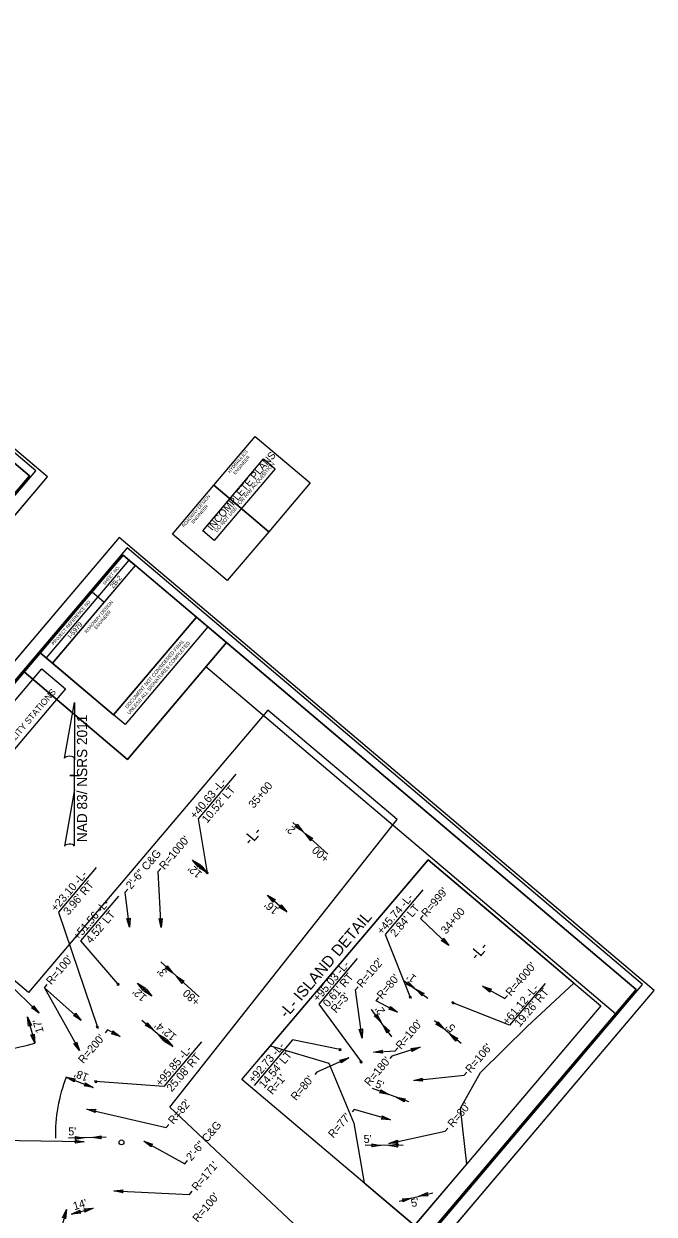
# Model space of a CAD drawing. Extents: x 1761753 to 1762923, y 422186 to 423380.
# Drawn here: x 1762529 to 1762923, y 422600 to 423344 of the extents above; entities that cross this region are included whole.
import ezdxf

# ---------------------------------------------------------------- set-up
doc = ezdxf.new("R2010")
doc.units = 0
for name, color, linetype in [('Default', 7, 'Continuous'), ('Matchline', 7, 'Continuous'), ('Old_Level_11', 7, 'Continuous'), ('Old_Level_2', 7, 'Continuous'), ('Prop Conc 2ft 6in Curb and Gutter', 7, 'Continuous'), ('Prop Conc 5in Monolithic Keyed In Island', 7, 'Continuous'), ('Prop Dimension Text', 7, 'Continuous'), ('Prop Grid Mask', 7, 'Continuous'), ('Prop Horizontal Alignment Station Label', 7, 'Continuous'), ('Prop Lane Lines', 7, 'Continuous'), ('Prop RDY Traffic Signal CELL', 7, 'Continuous'), ('Prop Shade Light', 7, 'Continuous'), ('Sheet Data Field CELL', 7, 'Continuous'), ('Sheet North Arrow CELL', 7, 'Continuous'), ('Sheet Plan CELL', 7, 'Continuous'), ('Sheet Plot Border Inside CELL', 7, 'Continuous'), ('Sheet Plot Border Outside CELL', 7, 'Continuous'), ('Sheet Symbology CELL', 7, 'Continuous')]:
    doc.layers.add(name, color=color, linetype=linetype)

# ---------------------------------------------------------------- blocks, each defined once
blk = doc.blocks.new('Terminator')
at = {"layer": 'Sheet Data Field CELL'}
blk.add_lwpolyline([(-9, 1.55), (0, 0), (-9.05, -1.6), (-7.9, 0)], close=True, dxfattribs=at)

msp = doc.modelspace()

# ---------------------------------------------------------------- linework, layer by layer
at = {"layer": 'Default'}
for p, q in [((1762643.7, 422813.72), (1762643.12, 422814.21)), ((1762644.53, 422813.02), (1762643.7, 422813.72)), ((1762588, 422744.01), (1762587.42, 422744.5)), ((1762588.84, 422743.31), (1762588, 422744.01)), ((1762770.61, 422736.01), (1762770.03, 422736.5)), ((1762771.44, 422735.31), (1762770.61, 422736.01)), ((1762797.3, 422732.43), (1762796.72, 422732.92)), ((1762798.13, 422731.73), (1762797.3, 422732.43)), ((1762575.18, 422717.23), (1762574.6, 422717.72)), ((1762576.01, 422716.53), (1762575.18, 422717.23)), ((1762726.66, 422703.17), (1762726.08, 422703.66)), ((1762727.49, 422702.47), (1762726.66, 422703.17)), ((1762739.9, 422695.46), (1762739.32, 422695.95)), ((1762740.74, 422694.76), (1762739.9, 422695.46)), ((1762574.1, 422683.22), (1762573.51, 422683.71)), ((1762574.93, 422682.51), (1762574.1, 422683.22))]:
    msp.add_line(p, q, dxfattribs=at)
at = {"layer": 'Matchline'}
for p, q in [((1762554.85, 422885.28), (1762561, 422920.05)), ((1762561.03, 422920.05), (1762561, 422920.05)), ((1762561.03, 422920.05), (1762561, 422920.05)), ((1762561.03, 422920.05), (1762561.03, 422884.2)), ((1762561.03, 422865.6), (1762561.03, 422885.25)), ((1762561.03, 422884.2), (1762561.03, 422885.21)), ((1762558.03, 422874.3), (1762558, 422874.3)), ((1762560.7, 422874.3), (1762558.03, 422874.3)), ((1762558.07, 422874.3), (1762564.07, 422874.3)), ((1762561.03, 422865.6), (1762554.77, 422830.16)), ((1762561.07, 422830.31), (1762561.03, 422865.6))]:
    msp.add_line(p, q, dxfattribs=at)
for centre, start_param, end_param in [((1762557.95, 422884.91), 0.216388, 2.908219), ((1762557.95, 422830.03), 0.201328, 3.141593)]:
    msp.add_ellipse(centre, major_axis=(3.17, -0.02), ratio=0.461098, start_param=start_param, end_param=end_param, dxfattribs=at)
at = {"layer": 'Old_Level_2'}
msp.add_lwpolyline([(1762648.26, 423021.24), (1762641.09, 423027.31), (1762679.1, 423072.18), (1762686.27, 423066.1)], close=True, dxfattribs=at)
at = {"layer": 'Prop Conc 2ft 6in Curb and Gutter'}
for points in [[(1762106.21, 422556.31), (1762536.95, 423064.78), (1762214.97, 423337.56), (1761784.22, 422829.09)], [(1762485.08, 422235.35), (1762915.83, 422743.82), (1762593.84, 423016.59), (1762163.09, 422508.12)]]:
    msp.add_lwpolyline(points, close=True, dxfattribs=at)
at = {"layer": 'Prop Conc 5in Monolithic Keyed In Island'}
msp.add_lwpolyline([(1762665.6, 422684.45), (1762781.88, 422821.7), (1762889.72, 422730.34), (1762773.44, 422593.08)], close=True, dxfattribs=at)
at = {"layer": 'Prop Dimension Text'}
for p, q in [((1762108.95, 422547.17), (1762544.23, 423060.98)), ((1762588.9, 423023.14), (1762153.62, 422509.33)), ((1762487.82, 422226.21), (1762923.1, 422740.02))]:
    msp.add_line(p, q, dxfattribs=at)
at = {"layer": 'Prop Grid Mask'}
for p, q in [((1762648, 423055.73), (1762682.32, 423026.66)), ((1762543.47, 422947.83), (1762595.2, 423008.89)), ((1762571.99, 422989.22), (1762579.63, 422982.77))]:
    msp.add_line(p, q, dxfattribs=at)
for points in [[(1762212.5, 423333.11), (1761824.66, 422875.29), (1762145.13, 422603.81), (1762532.96, 423061.62)], [(1762145.13, 422603.81), (1761824.66, 422875.28), (1762160.77, 423272.05), (1762206.57, 423233.25), (1762258.3, 423294.3), (1762532.96, 423061.62)], [(1762648, 423055.73), (1762673.85, 423086.25), (1762708.19, 423057.16), (1762682.34, 423026.64)], [(1762622.13, 423025.2), (1762648, 423055.73), (1762682.34, 423026.64), (1762656.46, 422996.12)], [(1762591.38, 423012.14), (1762203.53, 422554.33), (1762524, 422282.84), (1762911.83, 422740.65)], [(1762539.64, 422951.08), (1762591.38, 423012.14), (1762599.01, 423005.65), (1762547.3, 422944.6)], [(1762547.3, 422944.6), (1762599.02, 423005.65), (1762637.16, 422973.34), (1762585.44, 422912.29)], [(1762524, 422282.84), (1762203.54, 422554.31), (1762539.64, 422951.08), (1762585.45, 422912.29), (1762637.17, 422973.33), (1762911.83, 422740.65)]]:
    msp.add_lwpolyline(points, close=True, dxfattribs=at)
at = {"layer": 'Prop Horizontal Alignment Station Label'}
for points in [[(1762523.28, 422308.57), (1762722.11, 422543.28), (1762725.69, 422557.29), (1762715.43, 422577.81), (1762620.66, 422667), (1762762.51, 422846.79), (1762681.74, 422915.22), (1762532.27, 422738.78), (1762453.01, 422805.92), (1762420.01, 422792.47), (1762392.6, 422758.24), (1762237.08, 422551.03)], [(1762523.28, 422308.57), (1762722.11, 422543.28), (1762725.69, 422557.29), (1762715.43, 422577.81), (1762620.66, 422667), (1762762.51, 422846.79), (1762681.74, 422915.22), (1762532.27, 422738.78), (1762453.01, 422805.92), (1762420.01, 422792.47), (1762392.6, 422758.24), (1762237.08, 422551.03)], [(1762683.39, 422705.52), (1762719.82, 422694.67), (1762735.44, 422657.05), (1762741.95, 422619.76), (1762773.44, 422593.08), (1762806.05, 422631.57), (1762802.04, 422666.54), (1762814.53, 422688.79), (1762843.7, 422717.47), (1762872.94, 422744.56), (1762850.55, 422763.52), (1762781.88, 422821.7), (1762677.87, 422698.94)]]:
    msp.add_lwpolyline(points, close=True, dxfattribs=at)
at = {"layer": 'Prop Lane Lines'}
for centre, start, end in [((1762507.3, 422802.78), 264.4409, 286.87318), ((1762649.06, 422649.59), 158.69075, 181.12303)]:
    msp.add_arc(centre, 100, start, end, dxfattribs=at)
at = {"layer": 'Prop RDY Traffic Signal CELL'}
for points in [[(1761824.66, 422875.28), (1762145.13, 422603.81), (1762532.96, 423061.61), (1762277.04, 423278.41), (1762215.18, 423205.39), (1762150.64, 423260.08)], [(1762594.05, 422884.43), (1762655.92, 422957.46), (1762591.38, 423012.15), (1762529.51, 422939.11)], [(1762203.54, 422554.31), (1762524, 422282.84), (1762911.83, 422740.65), (1762655.91, 422957.45), (1762594.05, 422884.43), (1762529.51, 422939.11)]]:
    msp.add_lwpolyline(points, close=True, dxfattribs=at)
at = {"layer": 'Prop Shade Light'}
for p, q in [((1762585.45, 422912.29), (1762637.17, 422973.34)), ((1762585.45, 422912.29), (1762637.17, 422973.34)), ((1762637.17, 422973.33), (1762644.34, 422967.26)), ((1762637.17, 422973.33), (1762644.34, 422967.26)), ((1762644.34, 422967.26), (1762592.62, 422906.21)), ((1762644.34, 422967.26), (1762592.62, 422906.21)), ((1762592.62, 422906.21), (1762585.45, 422912.29)), ((1762592.62, 422906.21), (1762585.45, 422912.29))]:
    msp.add_line(p, q, dxfattribs=at)
at = {"layer": 'Sheet Data Field CELL'}
for points in [[(1762708.55, 422833.53), (1762705.03, 422838.08), (1762709.92, 422834.97), (1762708.7, 422834.72)], [(1762628.26, 422744.35), (1762624.73, 422748.9), (1762629.62, 422745.79), (1762628.4, 422745.54)], [(1762778.27, 422736.65), (1762774.26, 422740.78), (1762779.47, 422738.23), (1762778.29, 422737.85)], [(1762606.49, 422719.8), (1762610.18, 422715.39), (1762605.18, 422718.3), (1762606.38, 422718.6)], [(1762788, 422720.49), (1762791.69, 422716.08), (1762786.69, 422719), (1762787.89, 422719.3)], [(1762585.05, 422714.7), (1762589.59, 422711.17), (1762584.09, 422712.96), (1762585.2, 422713.51)], [(1762756.28, 422713.4), (1762753.67, 422718.52), (1762757.89, 422714.56), (1762756.65, 422714.54)], [(1762562.25, 422707.86), (1762564.15, 422702.43), (1762560.5, 422706.92), (1762561.74, 422706.78)], [(1762767.01, 422670.49), (1762762.01, 422673.34), (1762767.71, 422672.35), (1762766.69, 422671.65)], [(1762574, 422663.7), (1762568.7, 422665.94), (1762574.48, 422665.63), (1762573.55, 422664.81)], [(1762577.76, 422647.22), (1762572.07, 422648.08), (1762577.75, 422649.2), (1762577.05, 422648.18)], [(1762763.07, 422642.16), (1762757.41, 422643.19), (1762763.12, 422644.15), (1762762.39, 422643.15)], [(1762765.66, 422609.8), (1762771.4, 422610.2), (1762766.1, 422607.87), (1762766.57, 422609.02)]]:
    msp.add_lwpolyline(points, close=True, dxfattribs=at)
at = {"layer": 'Sheet North Arrow CELL'}
for points in [[(1762108.95, 422547.17), (1762544.23, 423060.98), (1762210.03, 423344.1), (1761774.75, 422830.29)], [(1762487.82, 422226.21), (1762923.1, 422740.02), (1762588.9, 423023.14), (1762153.62, 422509.33)]]:
    msp.add_lwpolyline(points, close=True, dxfattribs=at)
at = {"layer": 'Sheet Plan CELL'}
for p, q in [((1762719.19, 422825.11), (1762697.44, 422845.02)), ((1762643.83, 422813.62), (1762634.79, 422821.52)), ((1762643.12, 422814.21), (1762644.53, 422813.02)), ((1762644.37, 422814.25), (1762643.22, 422812.9)), ((1762681.5, 422799.57), (1762693.71, 422789.23)), ((1762638.79, 422736.02), (1762614.92, 422757.88)), ((1762542.28, 422741.77), (1762564.15, 422702.43)), ((1762587.42, 422744.5), (1762588.84, 422743.31)), ((1762588.67, 422744.54), (1762587.52, 422743.19)), ((1762600.39, 422744.52), (1762609.24, 422736.42)), ((1762767.01, 422746.06), (1762781.82, 422735.27)), ((1762770.03, 422736.5), (1762771.44, 422735.31)), ((1762771.28, 422736.54), (1762770.13, 422735.19)), ((1762759.22, 422711.1), (1762746.53, 422728.08)), ((1762796.72, 422732.92), (1762798.13, 422731.73)), ((1762797.97, 422732.97), (1762796.82, 422731.61)), ((1762531.72, 422723.45), (1762536.32, 422707.08)), ((1762603.05, 422721.43), (1762622.39, 422705.04)), ((1762802.61, 422706.83), (1762785.83, 422721.05)), ((1762574.6, 422717.72), (1762576.01, 422716.53)), ((1762575.84, 422717.76), (1762574.7, 422716.41)), ((1762726.08, 422703.66), (1762727.49, 422702.47)), ((1762727.32, 422703.71), (1762726.18, 422702.35)), ((1762739.32, 422695.95), (1762740.74, 422694.76)), ((1762740.57, 422696), (1762739.42, 422694.64)), ((1762555.89, 422685.93), (1762572.66, 422679.39)), ((1762573.51, 422683.71), (1762574.93, 422682.51)), ((1762574.76, 422683.75), (1762573.62, 422682.4)), ((1762769.89, 422670.51), (1762747.07, 422678.71)), ((1762567.08, 422645.49), (1762417.09, 422647.54)), ((1762580.85, 422648.25), (1762557.18, 422647.79)), ((1762766.21, 422643.11), (1762742.65, 422643.34)), ((1762763.74, 422608.33), (1762784.92, 422613.52)), ((1762559.18, 422600.27), (1762572.66, 422604.08))]:
    msp.add_line(p, q, dxfattribs=at)
msp.add_lwpolyline([(1762435.24, 422816.71), (1762540.64, 422941.12), (1762555.5, 422928.53), (1762450.1, 422804.12)], close=True, dxfattribs=at)
for points in [[(1762661.84, 422875.11), (1762638.25, 422847.26), (1762643.83, 422813.62)], [(1762574.55, 422816.84), (1762550.96, 422788.99), (1762575.3, 422717.12)], [(1762615.2, 422779.38), (1762613.37, 422814.33), (1762615.04, 422816.3)], [(1762595.42, 422779.54), (1762592.69, 422801.41), (1762594.35, 422803.38)], [(1762778.57, 422802.92), (1762754.97, 422775.07), (1762770.74, 422735.91)], [(1762588.4, 422798.92), (1762564.81, 422771.06), (1762588.13, 422743.9)], [(1762794.83, 422768.03), (1762777.09, 422784.96), (1762778.75, 422786.93)], [(1762737.6, 422759.94), (1762713.57, 422731.57), (1762740.03, 422695.36)], [(1762538.85, 422725.82), (1762518.65, 422745.52), (1762516.87, 422743.41)], [(1762565.23, 422721.27), (1762542.28, 422741.77), (1762543.94, 422743.74)], [(1762740.61, 422710.23), (1762736.56, 422740.33), (1762738.23, 422742.3)], [(1762854.95, 422744.42), (1762832.81, 422718.28), (1762797.43, 422732.33)], [(1762815.96, 422742.62), (1762829.8, 422734.98), (1762831.46, 422736.95)], [(1762762.87, 422726.56), (1762749.46, 422733.59), (1762751.12, 422735.56)], [(1762589.59, 422711.17), (1762581.68, 422715.39), (1762580.18, 422713.6)], [(1762640.31, 422707.92), (1762616.72, 422680.07), (1762574.22, 422683.11)], [(1762726.78, 422703.07), (1762697.23, 422709.09), (1762673.2, 422680.72)], [(1762747.86, 422701.47), (1762761.28, 422702.27), (1762762.94, 422704.24)], [(1762776.87, 422704.54), (1762759.14, 422699.03), (1762757.9, 422697.57)], [(1762732.33, 422697.97), (1762712.4, 422688.95), (1762711.16, 422687.49)], [(1762772.91, 422683.68), (1762804.51, 422687.05), (1762806.17, 422689.02)], [(1762568.7, 422665.94), (1762618.27, 422654.35), (1762619.94, 422656.32)], [(1762758.33, 422659.11), (1762735.7, 422665.54), (1762734.46, 422664.08)], [(1762757.41, 422644.37), (1762792.48, 422652.04), (1762794.14, 422654.01)], [(1762604.36, 422645.82), (1762630.03, 422631.71), (1762631.7, 422633.68)], [(1762585.58, 422614.8), (1762632.87, 422612.6), (1762634.53, 422614.57)], [(1762555.93, 422603.14), (1762544.31, 422561.05), (1762543.07, 422559.59)]]:
    msp.add_lwpolyline(points, dxfattribs=at)
at = {"layer": 'Sheet Plot Border Inside CELL'}
msp.add_circle((1762590.37, 422645.1), 1.5, dxfattribs=at)
at = {"layer": 'Sheet Symbology CELL'}
msp.add_lwpolyline([(1762536.93, 422298.1), (1762898.91, 422725.39), (1762642.99, 422942.19), (1762594.05, 422884.43), (1762529.51, 422939.11), (1762216.46, 422569.59)], close=True, dxfattribs=at)

# ---------------------------------------------------------------- block references
at = {"layer": 'Default'}
for p, xscale, yscale, rotation in [((1762703.55, 422839.43), 0.63, 0.6299999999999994, -42.476598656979), ((1762634.79, 422821.52), 0.6300000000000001, 0.6299999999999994, 138.81963379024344), ((1762643.83, 422813.62), 0.6300000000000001, 0.6299999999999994, -41.18036621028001), ((1762681.5, 422799.57), 0.6300000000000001, 0.6299999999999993, 139.73010343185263), ((1762693.71, 422789.23), 0.6299999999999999, 0.6299999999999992, -40.26989656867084), ((1762595.42, 422779.54), 0.6299999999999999, 0.6299999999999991, -82.88774720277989), ((1762615.2, 422779.38), 0.6300000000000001, 0.6299999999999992, -87.01025325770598), ((1762794.83, 422768.03), 0.6300000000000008, 0.6299999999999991, -43.652265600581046), ((1762622.52, 422750.92), 0.63, 0.6299999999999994, -42.476598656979), ((1762600.39, 422744.52), 0.6300000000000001, 0.6299999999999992, 137.52340134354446), ((1762773.46, 422741.37), 0.6300000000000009, 0.6299999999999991, -36.06628587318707), ((1762815.96, 422742.62), 0.6300000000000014, 0.6299999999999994, 151.07068200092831), ((1762609.24, 422736.42), 0.63, 0.6299999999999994, -42.476598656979), ((1762538.85, 422725.82), 0.6300000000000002, 0.6299999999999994, -44.279823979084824), ((1762762.87, 422726.56), 0.6300000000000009, 0.6299999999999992, -27.65573823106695), ((1762531.72, 422723.45), 0.6300000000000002, 0.6299999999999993, 105.6920301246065), ((1762565.23, 422721.27), 0.63, 0.6299999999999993, -41.78383857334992), ((1762752.47, 422720.13), 0.6300000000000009, 0.6299999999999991, -53.23612657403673), ((1762536.32, 422707.08), 0.63, 0.6299999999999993, -74.30796987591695), ((1762613.23, 422712.8), 0.6300000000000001, 0.6299999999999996, 139.73010349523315), ((1762740.61, 422710.23), 0.6300000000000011, 0.6299999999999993, -82.3413284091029), ((1762795.51, 422712.85), 0.6300000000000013, 0.6299999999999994, 139.7301034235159), ((1762622.39, 422705.04), 0.6300000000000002, 0.6299999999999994, -40.269896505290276), ((1762776.87, 422704.54), 0.6300000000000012, 0.6299999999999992, 17.267367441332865), ((1762732.33, 422697.97), 0.6299999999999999, 0.6299999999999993, 24.33091801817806), ((1762747.86, 422701.47), 0.6300000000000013, 0.6299999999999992, -176.60260094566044), ((1762555.89, 422685.93), 0.6300000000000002, 0.6299999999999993, 158.69075163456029), ((1762572.66, 422679.39), 0.63, 0.6299999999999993, -21.309248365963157), ((1762772.91, 422683.68), 0.6300000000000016, 0.6299999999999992, -173.90319093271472), ((1762757.3, 422675.03), 0.6300000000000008, 0.6299999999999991, -19.928352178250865), ((1762758.33, 422659.11), 0.6300000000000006, 0.6299999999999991, -15.851738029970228), ((1762567.07, 422647.98), 0.6300000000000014, 0.629999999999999, 1.123029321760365), ((1762567.08, 422645.49), 0.6300000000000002, 0.6299999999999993, -0.7799477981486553), ((1762604.36, 422645.82), 0.6300000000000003, 0.6299999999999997, 151.2204722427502), ((1762757.41, 422644.37), 0.6300000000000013, 0.6299999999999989, -167.66795626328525), ((1762752.41, 422643.24), 0.6300000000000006, 0.6299999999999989, -0.5600619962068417), ((1762585.58, 422614.8), 0.630000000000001, 0.6299999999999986, 177.33730820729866), ((1762776.26, 422611.39), 0.630000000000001, 0.6299999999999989, -166.2262934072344), ((1762555.93, 422603.14), 0.6300000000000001, 0.6299999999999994, 74.57170913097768), ((1762559.18, 422600.27), 0.6299999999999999, 0.6299999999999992, -164.2156049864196), ((1762572.66, 422604.08), 0.6300000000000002, 0.6299999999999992, 15.784395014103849)]:
    msp.add_blockref('Terminator', p, dxfattribs=dict(at, xscale=xscale, yscale=yscale, rotation=rotation))

# ---------------------------------------------------------------- texts
at = {"layer": 'Matchline'}
msp.add_text('NAD 83/ NSRS 2011', height=6.375, rotation=90, dxfattribs=at).set_placement((1762568.92, 422832.74))
at = {"layer": 'Old_Level_11'}
for s, p in [('2B-2', (1762585.16, 422991.03)), ('I-5979', (1762558.65, 422959.7))]:
    msp.add_text(s, height=3, rotation=49.73011, dxfattribs=at).set_placement(p)
at = {"layer": 'Old_Level_2'}
for s, height, p in [('INCOMPLETE PLANS', 4.608, (1762647.01, 423026.99)), ('DO NOT USE FOR R/W ACQUISITION', 2.304, (1762649.97, 423026.19))]:
    msp.add_text(s, height=height, rotation=49.7301, dxfattribs=at).set_placement(p)
at = {"layer": 'Prop Dimension Text'}
for s, height, rotation, p in [('+40.63 -L-', 5, 49.7301, (1762636.4, 422846.77)), ("10.52' LT", 5, 49.7301, (1762643.87, 422844.16)), ("2'", 5, 137.5234, (1762699.44, 422840.76)), ("R=1000'", 5, 49.7301, (1762617.23, 422815.11)), ('2\'-6" C&G', 5, 49.7301, (1762596.4, 422802.93)), ('+00', 5, 137.5234, (1762720.56, 422823)), ("12'", 5, 138.81963, (1762641.14, 422813.38)), ('+23.10 -L-', 5, 49.7301, (1762549.49, 422788.95)), ("3.96' RT", 5, 49.7301, (1762557.27, 422786.72)), ("R=999'", 5, 49.7301, (1762780.92, 422785.6)), ('+51.56 -L-', 5, 49.7301, (1762563.34, 422771.03)), ("16'", 5, 139.7301, (1762688.97, 422790.81)), ('+45.74 -L-', 5, 49.7301, (1762753.12, 422774.58)), ("2.84' LT", 5, 49.7301, (1762761.48, 422773.02)), ("4.52' LT", 5, 49.7301, (1762571.32, 422769.02)), ('-L- ISLAND DETAIL', 7, 49.7301, (1762693.47, 422722.24)), ("R=100'", 5, 49.7301, (1762546.57, 422743.16)), ('+95.03 -L-', 5, 49.7301, (1762713.19, 422732.6)), ("R=102'", 5, 49.7301, (1762740.63, 422741.35)), ("R=4000'", 5, 49.7301, (1762833.64, 422736.09)), ("3'", 5, 137.5234, (1762619.34, 422751.68)), ("0.61' RT", 5, 49.7301, (1762719.45, 422729.17)), ("R=80'", 5, 49.7301, (1762753.14, 422734.27)), ("1'", 5, 143.93371, (1762774.93, 422748.49)), ('+61.12 -L-', 5, 49.7301, (1762831.52, 422718.01)), ("19.26' RT", 5, 49.7301, (1762839.1, 422716.81)), ("12'", 5, 137.5234, (1762606.55, 422736.24)), ('+80', 5, 137.5234, (1762639.86, 422733.57)), ("R=3'", 5, 49.7301, (1762724.45, 422725.54)), ("2'", 5, 126.76387, (1762755.3, 422727.15)), ("17'", 5, 105.69203, (1762541.88, 422714.17)), ("4'", 5, 139.7301, (1762617.41, 422717.81)), ("R=100'", 5, 49.7301, (1762764.94, 422702.86)), ("R=200'", 5, 49.7301, (1762566.6, 422693.92)), ("12'", 5, 139.7301, (1762625.17, 422711.81)), ("5'", 5, 139.7301, (1762799.38, 422717.17)), ('+92.73 -L-', 5, 49.7301, (1762672.81, 422681.75)), ("R=106'", 5, 49.7301, (1762808.48, 422688.03)), ('+95.85 -L-', 5, 49.7301, (1762614.87, 422679.58)), ("25.08' RT", 5, 49.7301, (1762621.76, 422676.29)), ("14.54' LT", 5, 49.7301, (1762679.44, 422678.47)), ("R=180'", 5, 49.7301, (1762745.28, 422679.86)), ("18'", 5, 158.69075, (1762570.28, 422687.59)), ("R=1'", 5, 49.7301, (1762684.59, 422674.54)), ("R=80'", 5, 49.7301, (1762699.43, 422670.84)), ("5'", 5, 340.07165, (1762748.45, 422679.69)), ("R=82'", 5, 49.7301, (1762622.78, 422656.01)), ("R=80'", 5, 49.7301, (1762797.34, 422654.06)), ("R=77'", 5, 49.7301, (1762722.73, 422647.43)), ("5'", 5, 1.12303, (1762557.15, 422649.43)), ('2\'-6" C&G', 5, 49.7301, (1762634.01, 422633.16)), ("5'", 5, 1.12303, (1762741.69, 422644.7)), ("R=171'", 5, 49.7301, (1762637.54, 422614.45)), ("14'", 5, 15.7844, (1762560.89, 422602.7)), ("R=100'", 5, 49.7301, (1762638.04, 422594.8)), ("5'", 5, 13.77371, (1762771.82, 422604.52))]:
    msp.add_text(s, height=height, rotation=rotation, dxfattribs=at).set_placement(p)
at = {"layer": 'Prop Grid Mask'}
for s, p in [('HYDRAULICS', (1762658.09, 423063.15)), ('ENGINEER', (1762661.5, 423062.24)), ('ROADWAY DESIGN', (1762629.37, 423029.22)), ('ENGINEER', (1762635.28, 423031.54)), ('SHEET NO.', (1762579.92, 422993.16)), ('PROJECT REFERENCE NO.', (1762548.05, 422955.6)), ('ROADWAY DESIGN', (1762568.63, 422963.1)), ('ENGINEER', (1762574.64, 422965.53))]:
    msp.add_text(s, height=2, rotation=49.73011, dxfattribs=at).set_placement(p)
at = {"layer": 'Prop Shade Light'}
for s, p in [('DOCUMENT NOT CONSIDERED FINAL', (1762594.05, 422916.04)), ('DOCUMENT NOT CONSIDERED FINAL', (1762594.05, 422916.04)), ('UNLESS ALL SIGNATURES COMPLETED', (1762595.43, 422912.22)), ('UNLESS ALL SIGNATURES COMPLETED', (1762595.43, 422912.22))]:
    msp.add_text(s, height=2.2, rotation=49.7301, dxfattribs=at).set_placement(p)
at = {"layer": 'Sheet Plan CELL'}
msp.add_text('- SEE SHEET 4 FOR CURVE DATA AND EQUALITY STATIONS', height=4, rotation=49.7301, dxfattribs=at).set_placement((1762449.28, 422807.83))
at = {"layer": 'Sheet Plot Border Outside CELL'}
for s, height, p in [('35+00', 5, (1762672.97, 422853.49)), ('-L-', 7, (1762671.04, 422830.2)), ('34+00', 5, (1762793.13, 422774.85)), ('-L-', 7, (1762812.47, 422758.32))]:
    msp.add_text(s, height=height, rotation=49.7301, dxfattribs=at).set_placement(p)

doc.saveas('drawing.dxf')
